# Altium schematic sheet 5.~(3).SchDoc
size 420 x 297 mm
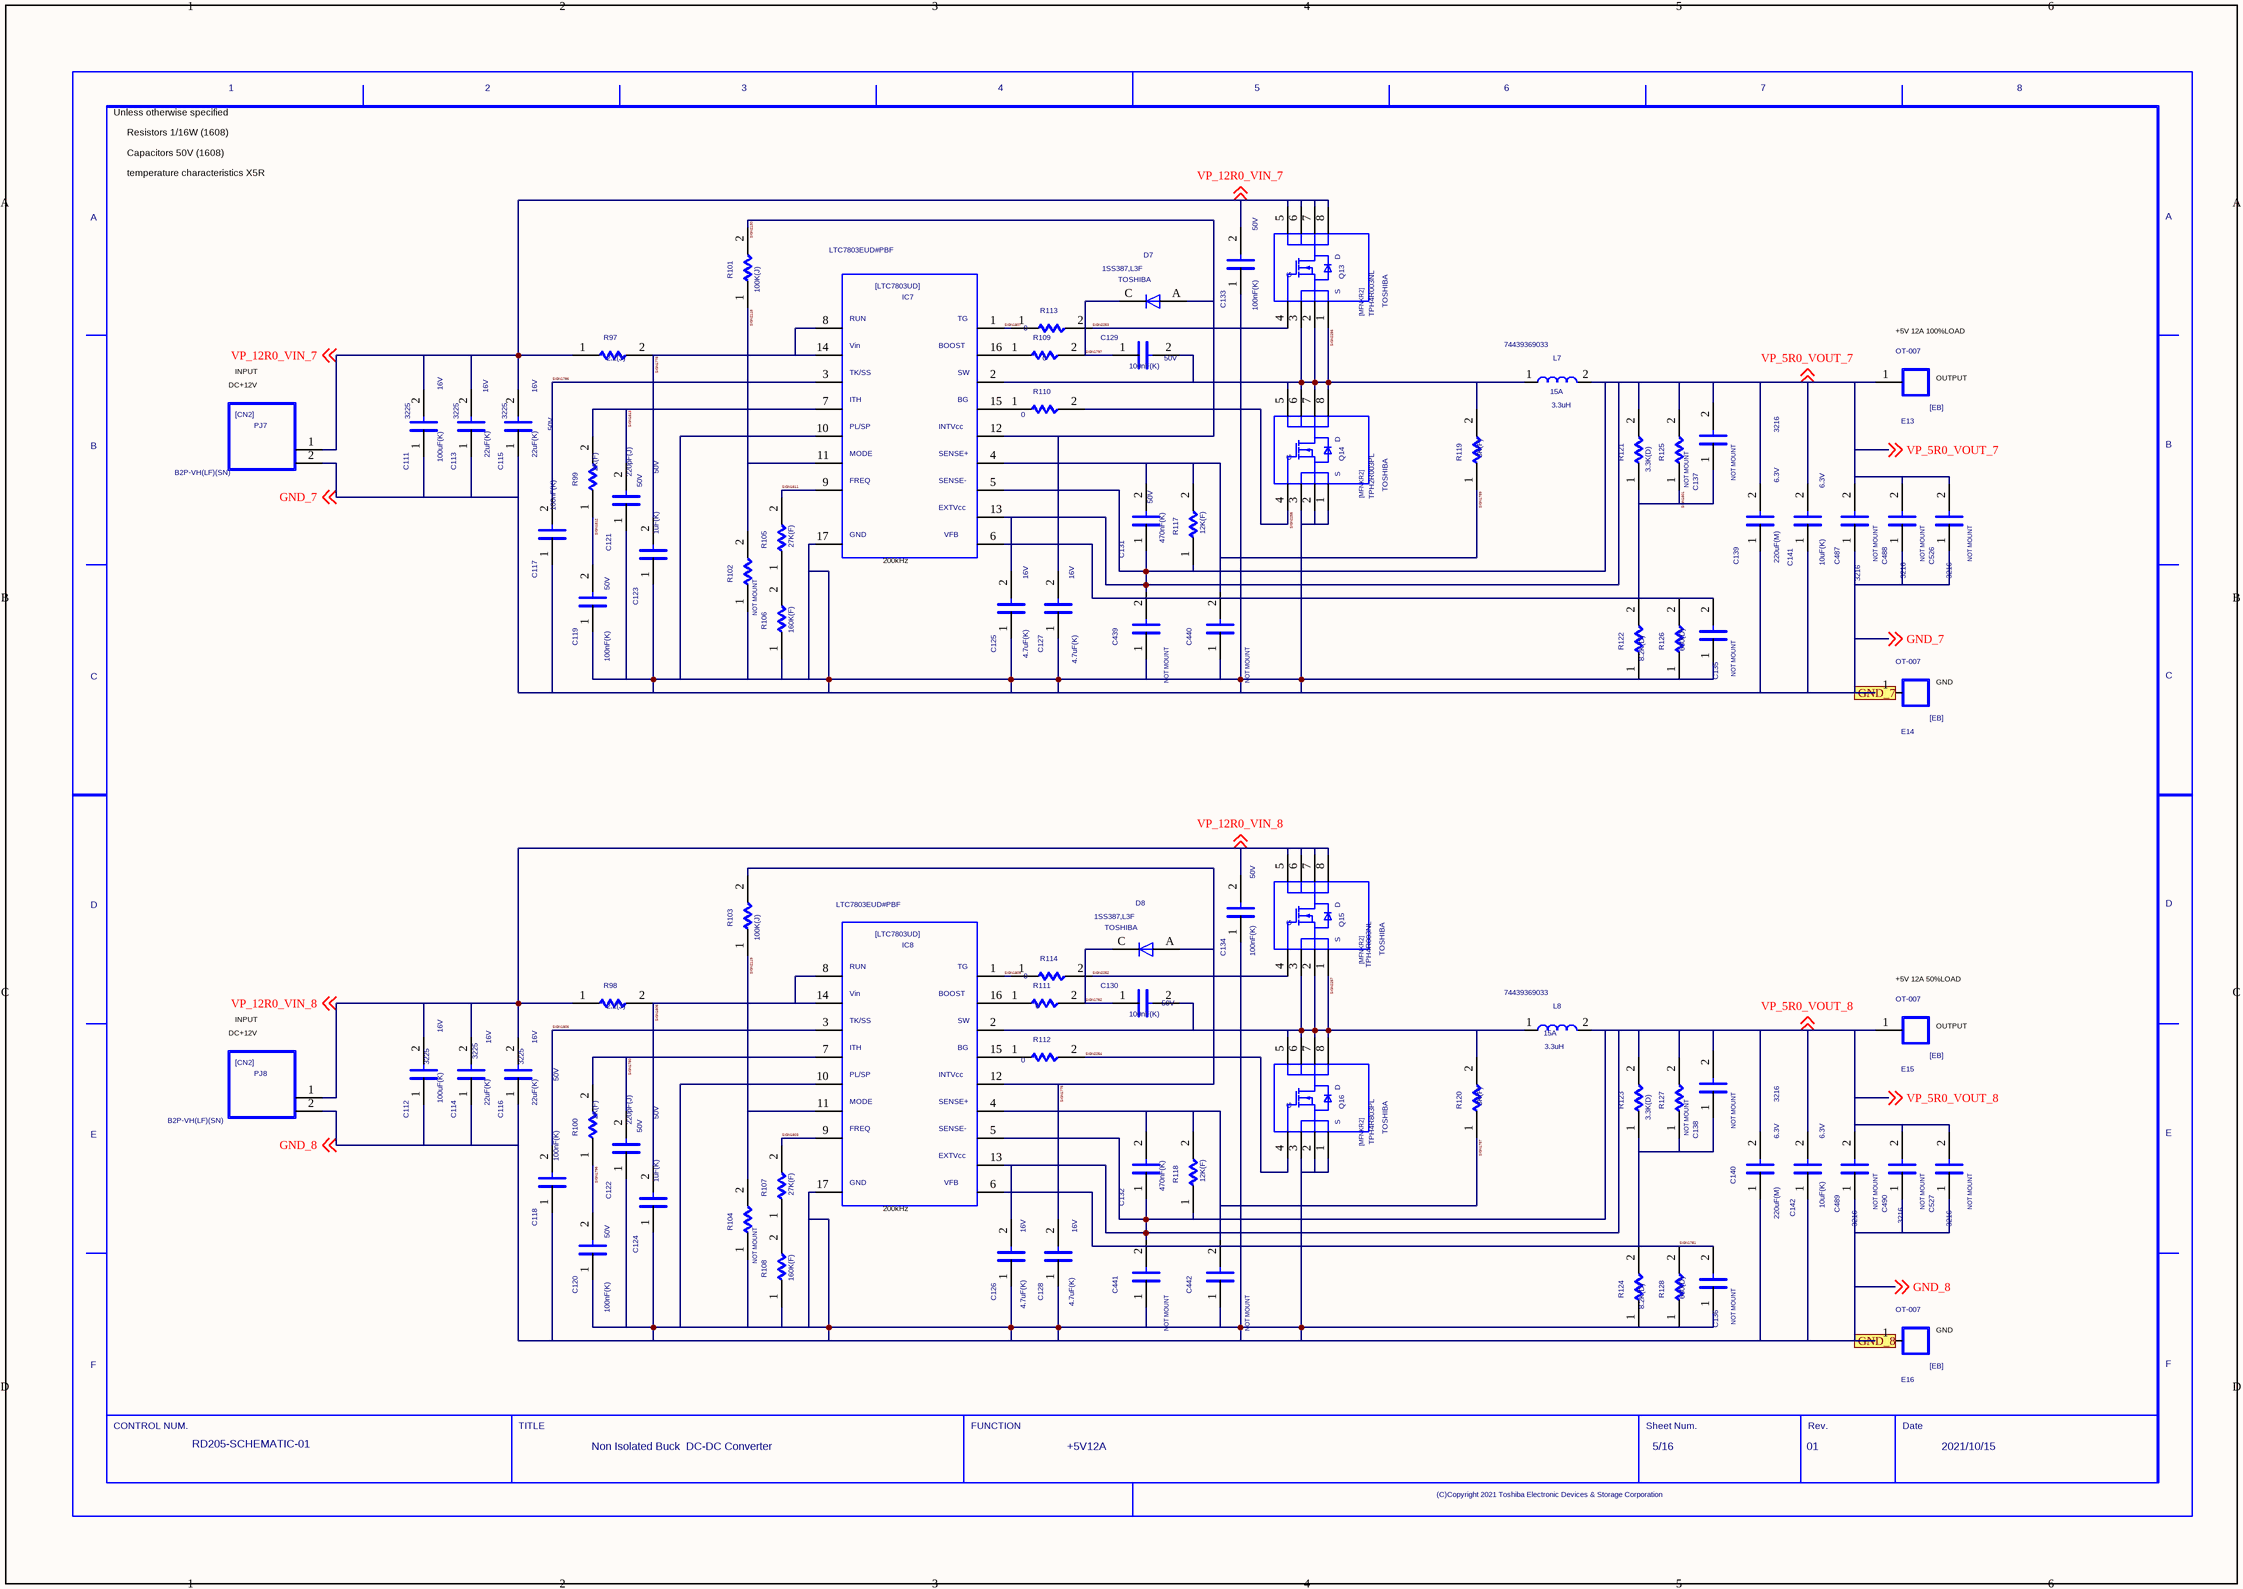
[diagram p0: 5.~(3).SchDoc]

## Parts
C111  SIZECODESMD: 3225  VAL2: 16V  VAL1: 100uF(K)  (hidden comment: C)
C112  SIZECODESMD: 3225  VAL2: 16V  VAL1: 100uF(K)  (hidden comment: C)
C113  SIZECODESMD: 3225  VAL2: 16V  VAL1: 22uF(K)  (hidden comment: C)
C114  SIZECODESMD: 3225  VAL2: 16V  VAL1: 22uF(K)  (hidden comment: C)
C115  SIZECODESMD: 3225  VAL2: 16V  VAL1: 22uF(K)  (hidden comment: C)
C116  SIZECODESMD: 3225  VAL2: 16V  VAL1: 22uF(K)  (hidden comment: C)
C117  VAL2: 50V  VAL1: 100nF(K)  (hidden comment: C)
C118  VAL2: 50V  VAL1: 100nF(K)  (hidden comment: C)
C119  VAL2: 50V  VAL1: 100nF(K)  (hidden comment: C)
C120  VAL2: 50V  VAL1: 100nF(K)  (hidden comment: C)
C121  VAL2: 50V  VAL1: 220pF(J)  (hidden comment: C)
C122  VAL2: 50V  VAL1: 220pF(J)  (hidden comment: C)
C123  VAL2: 50V  VAL1: 1uF(K)  (hidden comment: C)
C124  VAL2: 50V  VAL1: 1uF(K)  (hidden comment: C)
C125  VAL2: 16V  VAL1: 4.7uF(K)  (hidden comment: C)
C126  VAL2: 16V  VAL1: 4.7uF(K)  (hidden comment: C)
C127  VAL2: 16V  VAL1: 4.7uF(K)  (hidden comment: C)
C128  VAL2: 16V  VAL1: 4.7uF(K)  (hidden comment: C)
C129  VAL2: 50V  VAL1: 100nF(K)  (hidden comment: C)
C130  VAL2: 50V  VAL1: 100nF(K)  (hidden comment: C)
C131  VAL2: 50V  VAL1: 470nF(K)  (hidden comment: C)
C132  VAL1: 470nF(K)  (hidden comment: C)
C133  VAL2: 50V  VAL1: 100nF(K)  (hidden comment: C)
C134  VAL2: 50V  VAL1: 100nF(K)  (hidden comment: C)
C135  NOTMOUNT: NOT MOUNT  (hidden comment: C)
C136  NOTMOUNT: NOT MOUNT  (hidden comment: C)
C137  NOTMOUNT: NOT MOUNT  (hidden comment: C)
C138  NOTMOUNT: NOT MOUNT  (hidden comment: C)
C139  SIZECODESMD: 3216  VAL2: 6.3V  VAL1: 220uF(M)  (hidden comment: C)
C140  SIZECODESMD: 3216  VAL2: 6.3V  VAL1: 220uF(M)  (hidden comment: C)
C141  VAL2: 6.3V  VAL1: 10uF(K)  (hidden comment: C)
C142  VAL2: 6.3V  VAL1: 10uF(K)  (hidden comment: C)
C439  NOTMOUNT: NOT MOUNT  (hidden comment: C)
C440  NOTMOUNT: NOT MOUNT  (hidden comment: C)
C441  NOTMOUNT: NOT MOUNT  (hidden comment: C)
C442  NOTMOUNT: NOT MOUNT  (hidden comment: C)
C487  NOTMOUNT: NOT MOUNT  SIZECODESMD: 3216  (hidden comment: C)
C488  NOTMOUNT: NOT MOUNT  SIZECODESMD: 3216  (hidden comment: C)
C489  NOTMOUNT: NOT MOUNT  SIZECODESMD: 3216  (hidden comment: C)
C490  NOTMOUNT: NOT MOUNT  SIZECODESMD: 3216  (hidden comment: C)
C526  NOTMOUNT: NOT MOUNT  SIZECODESMD: 3216  (hidden comment: C)
C527  NOTMOUNT: NOT MOUNT  SIZECODESMD: 3216  (hidden comment: C)
D7  USERCOMPTEXT3: TOSHIBA  VAL3: 1SS387,L3F  (hidden comment: D)
D8  USERCOMPTEXT3: TOSHIBA  VAL3: 1SS387,L3F  (hidden comment: D)
E13  VAL3: OT-007  (hidden comment: EB)
E14  VAL3: OT-007  (hidden comment: EB)
E15  VAL3: OT-007  (hidden comment: EB)
E16  VAL3: OT-007  (hidden comment: EB)
IC7  VAL3: LTC7803EUD#PBF  (hidden comment: LTC7803UD)
IC8  VAL3: LTC7803EUD#PBF  (hidden comment: LTC7803UD)
L7  VAL3: 74439369033  VAL2: 15A  VAL1: 3.3uH  (hidden comment: L)
L8  VAL3: 74439369033  VAL2: 15A  VAL1: 3.3uH  (hidden comment: L)
PJ7  VAL3: B2P-VH(LF)(SN)  (hidden comment: CN2)
PJ8  VAL3: B2P-VH(LF)(SN)  (hidden comment: CN2)
Q13  USERCOMPTEXT3: TOSHIBA  VAL3: TPH4R003NL  (hidden comment: MFNKR2)
Q14  USERCOMPTEXT3: TOSHIBA  VAL3: TPH2R003PL  (hidden comment: MFNKR2)
Q15  USERCOMPTEXT3: TOSHIBA  VAL3: TPH4R003NL  (hidden comment: MFNKR2)
Q16  USERCOMPTEXT3: TOSHIBA  VAL3: TPH4R803PL  (hidden comment: MFNKR2)
R97  VAL1: 2.2(J)  (hidden comment: R)
R98  VAL1: 2.2(J)  (hidden comment: R)
R99  VAL1: 2K(F)  (hidden comment: R)
R100  VAL1: 2K(F)  (hidden comment: R)
R101  VAL1: 100K(J)  (hidden comment: R)
R102  NOTMOUNT: NOT MOUNT  (hidden comment: R)
R103  VAL1: 100K(J)  (hidden comment: R)
R104  NOTMOUNT: NOT MOUNT  (hidden comment: R)
R105  VAL1: 27K(F)  (hidden comment: R)
R106  VAL1: 160K(F)  (hidden comment: R)
R107  VAL1: 27K(F)  (hidden comment: R)
R108  VAL1: 160K(F)  (hidden comment: R)
R109  VAL1: 0  (hidden comment: R)
R110  VAL1: 0  (hidden comment: R)
R111  VAL1: 0  (hidden comment: R)
R112  VAL1: 0  (hidden comment: R)
R113  VAL1: 0  (hidden comment: R)
R114  VAL1: 0  (hidden comment: R)
R117  VAL1: 12K(F)  (hidden comment: R)
R118  VAL1: 12K(F)  (hidden comment: R)
R119  VAL1: 3K(F)  (hidden comment: R)
R120  VAL1: 3K(F)  (hidden comment: R)
R121  VAL1: 3.3K(D)  (hidden comment: R)
R122  VAL1: 8.2K(D)  (hidden comment: R)
R123  VAL1: 3.3K(D)  (hidden comment: R)
R124  VAL1: 8.2K(D)  (hidden comment: R)
R125  NOTMOUNT: NOT MOUNT  (hidden comment: R)
R126  VAL1: 680(D)  (hidden comment: R)
R127  NOTMOUNT: NOT MOUNT  (hidden comment: R)
R128  VAL1: 680(D)  (hidden comment: R)
U?  DATE: 2021/10/15  SHEETNUMBER: 5/16  TITLE: Non Isolated Buck / DC-DC Converter  REVISION: 01  DRAWINGNUMBER: RD205-SCHEMATIC-01  FUNCTION: +5V12A  (hidden comment: WAKU_DEF100)

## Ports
GND_7, GND_8

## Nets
GND_7: C111.1 C113.1 C115.1 C117.1 C119.1 C121.1 C123.1 C125.1 C127.1 C133.1 C135.1 C139.1 C141.1 C439.1 C440.1 C487.1 C488.1 C526.1 E14.1 IC7.10 IC7.17 PJ7.2 Q14.1 Q14.2 Q14.3 R102.1 R106.1 R122.1 R126.1 ; off-sheet GND_7, port GND_7
GND_8: C112.1 C114.1 C116.1 C118.1 C120.1 C122.1 C124.1 C126.1 C128.1 C134.1 C136.1 C140.1 C142.1 C441.1 C442.1 C489.1 C490.1 C527.1 E16.1 IC8.10 IC8.17 PJ8.2 Q16.1 Q16.2 Q16.3 R104.1 R108.1 R124.1 R128.1 ; off-sheet GND_8, port GND_8
SIGN1775: C128.2 D8.A IC8.12 R103.2
SIGN1778: C123.2 IC7.8 IC7.14 R97.2
SIGN1780: C122.2 IC8.7 R100.2
SIGN1781: C136.2 C138.1 IC8.6 R123.1 R124.2 R127.1 R128.2
SIGN1782: C130.1 D8.C R111.2
SIGN1786: C117.2 IC7.3
SIGN1787: C132.2 C442.2 IC8.4 R118.2 R120.1
SIGN1789: C131.2 C440.2 IC7.4 R117.2 R119.1
SIGN1796: C120.2 R100.1
SIGN1797: C129.1 D7.C R109.2
SIGN1801: C135.2 C137.1 IC7.6 R121.1 R122.2 R125.1 R126.2
SIGN1803: IC8.9 R107.2
SIGN1805: C124.2 IC8.8 IC8.14 R98.2
SIGN1806: C118.2 IC8.3
SIGN1807: IC7.1 R113.1
SIGN1809: IC8.1 R114.1
SIGN1811: IC7.9 R105.2
SIGN1812: C119.2 R99.1
SIGN1813: C121.2 IC7.7 R99.2
SIGN2118: IC7.11 R101.1 R102.2
SIGN2119: IC8.11 R103.1 R104.2
SIGN2130: C127.2 D7.A IC7.12 R101.2
SIGN2252: Q15.4 R114.2
SIGN2253: Q13.4 R113.2
SIGN2254: Q16.4 R112.2
SIGN2255: Q14.4 R110.2
SIGN2256: C129.2 IC7.2 L7.1 Q13.1 Q13.2 Q13.3 Q14.5 Q14.6 Q14.7 Q14.8 R119.2
SIGN2257: C130.2 IC8.2 L8.1 Q15.1 Q15.2 Q15.3 Q16.5 Q16.6 Q16.7 Q16.8 R120.2
VP_5R0_VOUT_7: C125.2 C131.1 C137.2 C139.2 C141.2 C439.2 C487.2 C488.2 C526.2 E13.1 IC7.5 IC7.13 L7.2 R117.1 R121.2 R125.2 ; off-sheet VP_5R0_VOUT_7
VP_5R0_VOUT_8: C126.2 C132.1 C138.2 C140.2 C142.2 C441.2 C489.2 C490.2 C527.2 E15.1 IC8.5 IC8.13 L8.2 R118.1 R123.2 R127.2 ; off-sheet VP_5R0_VOUT_8
VP_12R0_VIN_7: C111.2 C113.2 C115.2 C133.2 PJ7.1 Q13.5 Q13.6 Q13.7 Q13.8 R97.1 ; off-sheet VP_12R0_VIN_7
VP_12R0_VIN_8: C112.2 C114.2 C116.2 C134.2 PJ8.1 Q15.5 Q15.6 Q15.7 Q15.8 R98.1 ; off-sheet VP_12R0_VIN_8
NetIC7_15: IC7.15 R110.1
NetIC7_16: IC7.16 R109.1
NetIC8_15: IC8.15 R112.1
NetIC8_16: IC8.16 R111.1
NetR105_1: R105.1 R106.2
NetR107_1: R107.1 R108.2

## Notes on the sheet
- Unless otherwise specified
- Resistors 1/16W (1608)
- Capacitors 50V (1608)
- temperature characteristics X5R
- DC+12V
- INPUT
- (near E13) +5V 12A 100%LOAD
- (near E13) OUTPUT
- (near IC7) 200kHz
- (near E14) GND
- (near E15) +5V 12A 50%LOAD
- (near E15) OUTPUT
- (near IC8) 200kHz
- (near E16) GND

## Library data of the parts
C111 C112 = C: SQ_PART_MODEL: CON_100n; FNPARTSNAMEG: CHIP CERAMIC CAPACITOR (3225); USEINPARTSLIST: YES; OriginalSymbolOrigin: (2540,7620); MFSOLDERINGPROP: .; TEMPCHARACTERI2: B; MFFORMINGDIVP: KC; OUMECLASSIFICATION: セラミックコンデンサ; MFMOUNTSYMBOLP: 90; CDMASTERCADCELG: DC903A; PCODE: P03276001115; FNCLASSCODEG: P03-03; MAXGCOUNT: 1; RATEDVOLTAGE: 250; COMPONENTNAME: G36030160049; OUMEMAKER: KYC 京セラ; MFPACKAGEMETHOP: S; NOMINALCAPACITA: 100n; OUMEMAKERKATAMEI: CF32W5R104K250AT; CAPACITANCETOLE: K
C113-C116 = C: SQ_PART_MODEL: CON_22u; FNPARTSNAMEG: CHIP CERAMIC CAPACITOR (3225); USEINPARTSLIST: YES; OriginalSymbolOrigin: (2540,7620); MFSOLDERINGPROP: .; TEMPCHARACTERI2: B; MFFORMINGDIVP: KC; OUMECLASSIFICATION: セラミックコンデンサ; MFMOUNTSYMBOLP: 80; CDMASTERCADCELG: DC903A; PCODE: P03043035626; FNCLASSCODEG: P03-03; MAXGCOUNT: 1; RATEDVOLTAGE: 6.3; COMPONENTNAME: G36030119054; OUMEMAKER: TYD 太陽誘電; MFPACKAGEMETHOP: S; NOMINALCAPACITA: 22u; OUMEMAKERKATAMEI: JMK325BJ226KM-T; CAPACITANCETOLE: K
C117-C120 C129 C130 C133 C134 = C: SQ_PART_MODEL: CON_100n; FNPARTSNAMEG: CHIP CERAMIC CAPACITOR (1608); USEINPARTSLIST: YES; OriginalSymbolOrigin: (2540,7620); MFSOLDERINGPROP: .; TEMPCHARACTERI2: B; MFFORMINGDIVP: KC; OUMECLASSIFICATION: セラミックコンデンサ; SIZECODESMD: 1608; MFMOUNTSYMBOLP: 80; CDMASTERCADCELG: C8100E; PCODE: P03B000000E4; FNCLASSCODEG: P03-03; MAXGCOUNT: 1; RATEDVOLTAGE: 16; COMPONENTNAME: GDM030000598; OUMEMAKER: MRT 村田製作所; MFPACKAGEMETHOP: S; NOMINALCAPACITA: 100n; OUMEMAKERKATAMEI: GRM188B11C104KA01C; CAPACITANCETOLE: K
C121 = C: SQ_PART_MODEL: CON_220p; FNPARTSNAMEG: CHIP CERAMIC CAPACITOR (1608); USEINPARTSLIST: YES; OriginalSymbolOrigin: (2540,7620); CDMASTERCADCELG: C8100E; MFSOLDERINGPROP: .; TEMPCHARACTERI2: CH; MFFORMINGDIVP: KC; OUMECLASSIFICATION: セラミックコンデンサ; SIZECODESMD: 1608; MFMOUNTSYMBOLP: 80; PCODE: P03039269127; FNCLASSCODEG: P03-03; MAXGCOUNT: 1; RATEDVOLTAGE: 50; COMPONENTNAME: G36030011488; OUMEMAKER: KYC 京セラ; MFPACKAGEMETHOP: S; NOMINALCAPACITA: 220p; OUMEMAKERKATAMEI: CM105CH221J50AT; CAPACITANCETOLE: J
C122 = C: SQ_PART_MODEL: CON_220p; FNPARTSNAMEG: CHIP CERAMIC CAPACITOR (1608); USEINPARTSLIST: YES; OriginalSymbolOrigin: (2540,7620); MFSOLDERINGPROP: .; TEMPCHARACTERI2: CH; MFFORMINGDIVP: KC; OUMECLASSIFICATION: セラミックコンデンサ; SIZECODESMD: 1608; MFMOUNTSYMBOLP: 80; CDMASTERCADCELG: C8100E; PCODE: P03039269127; FNCLASSCODEG: P03-03; MAXGCOUNT: 1; RATEDVOLTAGE: 50; COMPONENTNAME: G36030011488; OUMEMAKER: KYC 京セラ; MFPACKAGEMETHOP: S; NOMINALCAPACITA: 220p; OUMEMAKERKATAMEI: CM105CH221J50AT; CAPACITANCETOLE: J
C123 C124 = C: SQ_PART_MODEL: CON_1u; FNPARTSNAMEG: CHIP CERAMIC CAPACITOR (1608); USEINPARTSLIST: YES; OriginalSymbolOrigin: (2540,7620); MFSOLDERINGPROP: .; TEMPCHARACTERI2: B; MFFORMINGDIVP: KC; OUMECLASSIFICATION: セラミックコンデンサ; SIZECODESMD: 1608; MFMOUNTSYMBOLP: 80; CDMASTERCADCELG: C8100E; PCODE: P03039ACE122; FNCLASSCODEG: P03-03; MAXGCOUNT: 1; RATEDVOLTAGE: 6.3; COMPONENTNAME: G36030104159; OUMEMAKER: KYC 京セラ; MFPACKAGEMETHOP: S; NOMINALCAPACITA: 1u; OUMEMAKERKATAMEI: CM105B105K06ATN; CAPACITANCETOLE: K
C125 C126 = C: SQ_PART_MODEL: CON_4.7u; FNPARTSNAMEG: CHIP CERAMIC CAPACITOR (1608); USEINPARTSLIST: YES; OriginalSymbolOrigin: (2540,7620); PCODE: P03B000000MS; MFSOLDERINGPROP: .; TEMPCHARACTERI2: B; MFFORMINGDIVP: KC; OUMECLASSIFICATION: セラミックコンデンサ; SIZECODESMD: 1608; MFMOUNTSYMBOLP: 80; CDMASTERCADCELG: C8100E; FNCLASSCODEG: P03-03; MAXGCOUNT: 1; RATEDVOLTAGE: 4; COMPONENTNAME: GDM030000053; OUMEMAKER: KYC 京セラ; MFPACKAGEMETHOP: S; NOMINALCAPACITA: 4.7u; OUMEMAKERKATAMEI: CM105B475M04AT; CAPACITANCETOLE: M
C127 C128 = C: SQ_PART_MODEL: CON_4.7u; FNPARTSNAMEG: CHIP CERAMIC CAPACITOR (1608); USEINPARTSLIST: YES; OriginalSymbolOrigin: (2540,7620); MFSOLDERINGPROP: .; TEMPCHARACTERI2: B; MFFORMINGDIVP: KC; OUMECLASSIFICATION: セラミックコンデンサ; SIZECODESMD: 1608; MFMOUNTSYMBOLP: 80; CDMASTERCADCELG: C8100E; PCODE: P03B000000MS; FNCLASSCODEG: P03-03; MAXGCOUNT: 1; RATEDVOLTAGE: 4; COMPONENTNAME: GDM030000053; OUMEMAKER: KYC 京セラ; MFPACKAGEMETHOP: S; NOMINALCAPACITA: 4.7u; OUMEMAKERKATAMEI: CM105B475M04AT; CAPACITANCETOLE: M
C131 = C: SQ_PART_MODEL: CON_470n; FNPARTSNAMEG: CHIP CERAMIC CAPACITOR (1608); USEINPARTSLIST: YES; OriginalSymbolOrigin: (2540,7620); MFSOLDERINGPROP: .; TEMPCHARACTERI2: B; MFFORMINGDIVP: KC; OUMECLASSIFICATION: セラミックコンデンサ; SIZECODESMD: 1608; MFMOUNTSYMBOLP: 80; CDMASTERCADCELG: C8100E; PCODE: P03039ABG127; FNCLASSCODEG: P03-03; MAXGCOUNT: 1; RATEDVOLTAGE: 10; COMPONENTNAME: GDM030001129; OUMEMAKER: KYC 京セラ; MFPACKAGEMETHOP: S; NOMINALCAPACITA: 470n; OUMEMAKERKATAMEI: CM105B474K10AT; CAPACITANCETOLE: K
C132 = C: SQ_PART_MODEL: CON_470n; FNPARTSNAMEG: CHIP CERAMIC CAPACITOR (1608); USEINPARTSLIST: YES; OriginalSymbolOrigin: (2540,7620); MFSOLDERINGPROP: .; TEMPCHARACTERI2: B; MFFORMINGDIVP: KC; OUMECLASSIFICATION: セラミックコンデンサ; SIZECODESMD: 1608; MFMOUNTSYMBOLP: 80; CDMASTERCADCELG: C8100E; PCODE: P03039ABG127; FNCLASSCODEG: P03-03; MAXGCOUNT: 1; RATEDVOLTAGE: 10; COMPONENTNAME: GDM030001129; OUMEMAKER: KYC 京セラ; MFPACKAGEMETHOP: S; NOMINALCAPACITA: 470n; OUMEMAKERKATAMEI: CM105B474K10AT; VAL2: 50V; CAPACITANCETOLE: K
C135-C138 = C: SQ_PART_MODEL: CON_100p; FNPARTSNAMEG: CHIP CERAMIC CAPACITOR (1608); USEINPARTSLIST: YES; OriginalSymbolOrigin: (2540,7620); TOLERANCE: J; ASIMVALUE: 100P; MFSOLDERINGPROP: .; TEMPCHARACTERI2: CH; MFFORMINGDIVP: KC; OUMECLASSIFICATION: セラミックコンデンサ; SIZECODESMD: 1608; MFMOUNTSYMBOLP: 80; CDMASTERCADCELG: C8100E; PCODE: P03039177125; FNCLASSCODEG: P03-03; MAXGCOUNT: 1; RATEDVOLTAGE: 50; COMPONENTNAME: G36030011365; OUMEMAKER: KYC 京セラ; MFPACKAGEMETHOP: S; OUMEMAKERKATAMEI: CM105CH101J50AT; VAL2: 50V; VAL1: 100pF(J)
C139 C140 = C: SQ_PART_MODEL: CON_22u; FNPARTSNAMEG: CHIP CERAMIC CAPACITOR (3216); USEINPARTSLIST: YES; OriginalSymbolOrigin: (2540,7620); MFSOLDERINGPROP: .; TEMPCHARACTERI2: B; MFFORMINGDIVP: KC; OUMECLASSIFICATION: セラミックコンデンサ; MFMOUNTSYMBOLP: 80; CDMASTERCADCELG: DC901A; PCODE: P03B0000004V; FNCLASSCODEG: P03-03; MAXGCOUNT: 1; RATEDVOLTAGE: 6.3; COMPONENTNAME: GDM030000020; OUMEMAKER: KYC 京セラ; MFPACKAGEMETHOP: S; NOMINALCAPACITA: 22u; OUMEMAKERKATAMEI: CM316B226M06AT; CAPACITANCETOLE: M
C141 C142 = C: SQ_PART_MODEL: CON_1u; FNPARTSNAMEG: CHIP CERAMIC CAPACITOR (1608); PARTCOMMENT: 代表セル<KC0008> がフットプリントに登録されていません。; USEINPARTSLIST: YES; OriginalSymbolOrigin: (2540,7620); MFSOLDERINGPROP: .; TEMPCHARACTERI2: B; MFFORMINGDIVP: KC; OUMECLASSIFICATION: セラミックコンデンサ; SIZECODESMD: 1608; MFMOUNTSYMBOLP: 80; CDMASTERCADCELG: KC0008; PCODE: P03B000000ZQ; FNCLASSCODEG: P03-03; MAXGCOUNT: 1; RATEDVOLTAGE: 6.3; COMPONENTNAME: GDM030000202; OUMEMAKER: MRT 村田製作所; MFPACKAGEMETHOP: S; NOMINALCAPACITA: 1u; OUMEMAKERKATAMEI: GRM185B10J105KE21D; CAPACITANCETOLE: K
C439-C442 = C: SQ_PART_MODEL: CON_220n; FNPARTSNAMEG: CHIP CERAMIC CAPACITOR (1608); PARTCOMMENT: 代表セル<KC0008> がフットプリントに登録されていません。; USEINPARTSLIST: YES; OriginalSymbolOrigin: (2540,7620); MFSOLDERINGPROP: .; TEMPCHARACTERI2: B; MFFORMINGDIVP: KC; OUMECLASSIFICATION: セラミックコンデンサ; SIZECODESMD: 1608; MFMOUNTSYMBOLP: 80; CDMASTERCADCELG: KC0008; PCODE: P03B000001L3; FNCLASSCODEG: P03-03; MAXGCOUNT: 1; RATEDVOLTAGE: 16; COMPONENTNAME: GDM030001129; OUMEMAKER: MRT 村田製作所; MFPACKAGEMETHOP: S; NOMINALCAPACITA: 220n; OUMEMAKERKATAMEI: GRM188B11C224KA01D; VAL2: 16V; VAL1: 220nF(K); CAPACITANCETOLE: K
C487-C490 C526 C527 = C: SQ_PART_MODEL: CON_22u; FNPARTSNAMEG: CHIP CERAMIC CAPACITOR (3216); USEINPARTSLIST: YES; OriginalSymbolOrigin: (2540,7620); MFSOLDERINGPROP: .; TEMPCHARACTERI2: B; MFFORMINGDIVP: KC; OUMECLASSIFICATION: セラミックコンデンサ; MFMOUNTSYMBOLP: 80; CDMASTERCADCELG: DC901A; PCODE: P03B0000004V; FNCLASSCODEG: P03-03; MAXGCOUNT: 1; RATEDVOLTAGE: 6.3; COMPONENTNAME: GDM030000020; OUMEMAKER: KYC 京セラ; MFPACKAGEMETHOP: S; NOMINALCAPACITA: 22u; OUMEMAKERKATAMEI: CM316B226M06AT; VAL2: 6.3V; VAL1: 22uF(M); CAPACITANCETOLE: M
D7 D8 = D: FNPARTSNAMEG: DIODE; USEINPARTSLIST: YES; PARTNAME: GDM420000143; SAVEAREA0: -565,-171,12979,8058; SAVECOUNT: 1; TIME: 14:49:55; UPDATEUSER: 19870035; UPDATETIME: 14:20:16; OriginalSymbolOrigin: (5080,5080); FORWARDVOLTAGEM: 0; MAXREVERSEVOLTA: 80; COMPONENTNAME: GDM420000143_package; MFSOLDERINGPROP: .; OUMEMAKER: TSB 東芝（ＹＰＳＳ）; QUADMODEL: dummymodel; MFPACKAGEMETHOP: S; MFFORMINGDIVP: MM; MOUNTINGFORMSMD: SMD; OUMECLASSIFICATION: 小信号ダイオード; OUMEMAKERKATAMEI: 1SS387(TPH3,F); CDMASTERCADCELG: D8101D; PCODE: P42B0000008E; FNCLASSCODEG: P42-01
E13-E16 = EB: FNPARTSNAMEG: TERMINAL; USEINPARTSLIST: YES; PARTNAME: 5P9L1232P001; OUMEPARTTYPE: TB; OriginalSymbolOrigin: (2540,12700); COMPONENTNAME: 5P9L1232P001_package; MAXGCOUNT: 1; MFSOLDERINGPROP: .; OUMEMAKER: オサダ; QUADMODEL: dummymodel; MFPACKAGEMETHOP: I; MFFORMINGDIVP: OD; OUMECLASSIFICATION: 端子台、端子板; CDMASTERCADCELG: DE0009; KIND: PBS; PCODE: P29045001117; TERMINALSTYLE: SC; FNCLASSCODEG: P29-01
IC7 IC8 = LTC7803UD: USEINPARTSLIST: YES; SAVECOUNT: 29; SAVEAREA0: -53177,0,89020,58420; TIME: 16:14:14; UPDATEUSER: q91866sr; UPDATETIME: 13:15:36; OriginalSymbolOrigin: (5080,55880); MAXGCOUNT: 1; COMPONENTNAME: LTC7803UD_LTC7803UD; OUMEMAKER: ANALOG DEVICES
L7 L8 = L: USEINPARTSLIST: YES; OriginalSymbolOrigin: (2540,5080); MAXGCOUNT: 1; COMPONENTNAME: L_L; OUMEMAKER: WURTH
PJ7 PJ8 = CN2: FNPARTSNAMEG: 3.96PITCH NYLON CONNECTOR; USEINPARTSLIST: YES; PARTNAME: G36220114012; OUMEPARTTYPE: CN; OriginalSymbolOrigin: (2540,15240); MAXGCOUNT: 1; RATEDCURRENT: 7; COMPONENTNAME: G36220114012_package; MFSOLDERINGPROP: .; OUMEMAKER: JST 日本圧着端子製造; NUMBEROFCONTACT: 2; QUADMODEL: dummymodel; MFPACKAGEMETHOP: I; MFFORMINGDIVP: CU; CONTACTPITCH: 3.96m; OUMEMAKERKATAMEI: B2P-VH; CDMASTERCADCELG: DPJ514; PCODE: P22346001114; TERMINALSTYLE: PW; FNCLASSCODEG: P22-10
Q13-Q16 = MFNKR2: USEINPARTSLIST: YES; PARTNAME: TPH6R003NL; SAVEAREA0: -9199,-39,32138,22820; TIME: 18:57:44; UPDATEUSER: q91866sr; UPDATETIME: 12:36:02; SAVECOUNT: 10; OriginalSymbolOrigin: (5080,20320); MAXGCOUNT: 1; COMPONENTNAME: MFNKR2_MFNKR2
R97 R98 = R: SQ_PART_MODEL: RES_2.2; FNPARTSNAMEG: CHIP RESISTOR (1608); USEINPARTSLIST: YES; OriginalSymbolOrigin: (5080,5080); TOLERANCE: J; ASIMVALUE: 2.2; MAXGCOUNT: 1; COMPONENTNAME: G36010011507; MFSOLDERINGPROP: .; OUMEMAKER: NAE 松下電子部品; MFPACKAGEMETHOP: S; MFFORMINGDIVP: KC; MOUNTINGFORMSMD: SMD; OUMECLASSIFICATION: 表面実装用固定抵抗器; MFMOUNTSYMBOLP: 80; POWERRATING: 63m; OUMEMAKERKATAMEI: ERJ3GEYJ2R2V; NUMBEROFELEMENT: 0; VAL2: 62.5mW; CDMASTERCADCELG: DR802R; PCODE: P01042157622; FNCLASSCODEG: P01-08
R99 R100 = R: SQ_PART_MODEL: RES_2K; FNPARTSNAMEG: CHIP RESISTOR (1608); USEINPARTSLIST: YES; OriginalSymbolOrigin: (5080,5080); MAXGCOUNT: 1; COMPONENTNAME: G36010027A10; MFSOLDERINGPROP: .; OUMEMAKER: KAM 釜屋電機; MFPACKAGEMETHOP: S; MFFORMINGDIVP: KC; MOUNTINGFORMSMD: SMD; OUMECLASSIFICATION: 表面実装用固定抵抗器; RESISTANCETOLER: F; MFMOUNTSYMBOLP: 80; POWERRATING: 63m; OUMEMAKERKATAMEI: RMC1/16-202FTP; NOMINALRESISTAN: 2K; NUMBEROFELEMENT: 0; VAL2: 62.5mW; CDMASTERCADCELG: DR802R; PCODE: P01042243325; FNCLASSCODEG: P01-08
R101 R103 = R: SQ_PART_MODEL: RES_100K; FNPARTSNAMEG: CHIP RESISTOR (1608); USEINPARTSLIST: YES; OriginalSymbolOrigin: (5080,5080); TOLERANCE: J; ASIMVALUE: 100K; MFSOLDERINGPROP: .; MFPACKAGEMETHOP: S; MFFORMINGDIVP: KC; MOUNTINGFORMSMD: SMD; MFMOUNTSYMBOLP: 80; NUMBEROFELEMENT: 0; PCODE: P01042047220; MAXGCOUNT: 1; COMPONENTNAME: G36010011057; OUMEMAKER: HDK 北陸電気工業; OUMECLASSIFICATION: 表面実装用固定抵抗器; POWERRATING: 63m; OUMEMAKERKATAMEI: CR1/16 104JV; VAL2: 62.5mW; CDMASTERCADCELG: DR802R; FNCLASSCODEG: P01-08
R102 R104 = R: SQ_PART_MODEL: RES_10; FNPARTSNAMEG: CHIP RESISTOR (1608); USEINPARTSLIST: YES; OriginalSymbolOrigin: (5080,5080); TOLERANCE: F; ASIMVALUE: 10; MFSOLDERINGPROP: .; MFPACKAGEMETHOP: S; MFFORMINGDIVP: KC; MOUNTINGFORMSMD: SMD; MFMOUNTSYMBOLP: 80; NUMBEROFELEMENT: 0; PCODE: P01042036620; MAXGCOUNT: 1; COMPONENTNAME: G36010104063; OUMEMAKER: NAE 松下電子部品; OUMECLASSIFICATION: 表面実装用固定抵抗器; POWERRATING: 63m; OUMEMAKERKATAMEI: ERJ3GEYF100V; VAL2: 62.5mW; VAL1: 10(F); CDMASTERCADCELG: DR802R; FNCLASSCODEG: P01-08
R105 R107 = R: SQ_PART_MODEL: RES_27K; FNPARTSNAMEG: CHIP RESISTOR (1608); USEINPARTSLIST: YES; OriginalSymbolOrigin: (5080,5080); MAXGCOUNT: 1; TOLERANCE: F; COMPONENTNAME: G36010027195; MFSOLDERINGPROP: .; OUMEMAKER: NAE 松下電子部品; MFPACKAGEMETHOP: S; MFFORMINGDIVP: KC; MOUNTINGFORMSMD: SMD; OUMECLASSIFICATION: 表面実装用固定抵抗器; ASIMVALUE: 27K; MFMOUNTSYMBOLP: 80; POWERRATING: 63m; OUMEMAKERKATAMEI: ERJ3GEYF273V; NUMBEROFELEMENT: 0; VAL2: 62.5mW; CDMASTERCADCELG: DR802R; PCODE: P01042508622; FNCLASSCODEG: P01-08
R106 R108 = R: SQ_PART_MODEL: RES_160K; FNPARTSNAMEG: CHIP RESISTOR (1608); USEINPARTSLIST: YES; OriginalSymbolOrigin: (5080,5080); MAXGCOUNT: 1; COMPONENTNAME: G51011061108; MFSOLDERINGPROP: .; OUMEMAKER: HDK 北陸電気工業; MFPACKAGEMETHOP: S; MFFORMINGDIVP: KC; MOUNTINGFORMSMD: SMD; OUMECLASSIFICATION: 表面実装用固定抵抗器; RESISTANCETOLER: F; MFMOUNTSYMBOLP: 80; POWERRATING: 63m; OUMEMAKERKATAMEI: CR1/16 164FV; NOMINALRESISTAN: 160K; NUMBEROFELEMENT: 0; VAL2: 62.5mW; CDMASTERCADCELG: DR802R; PCODE: P01042125225; FNCLASSCODEG: P01-08
R109 R111 = R: SQ_PART_MODEL: RES_10; FNPARTSNAMEG: CHIP RESISTOR (1608); USEINPARTSLIST: YES; OriginalSymbolOrigin: (5080,5080); TOLERANCE: F; ASIMVALUE: 10; MFSOLDERINGPROP: .; MFPACKAGEMETHOP: S; MFFORMINGDIVP: KC; MOUNTINGFORMSMD: SMD; MFMOUNTSYMBOLP: 80; PCODE: P01042036620; MAXGCOUNT: 1; COMPONENTNAME: G36010104063; OUMEMAKER: NAE 松下電子部品; OUMECLASSIFICATION: 表面実装用固定抵抗器; POWERRATING: 63m; OUMEMAKERKATAMEI: ERJ3GEYF100V; VAL2: 62.5mW; CDMASTERCADCELG: DR802R; FNCLASSCODEG: P01-08
R110 R112-R114 = R: SQ_PART_MODEL: RES_10; FNPARTSNAMEG: CHIP RESISTOR (2012); USEINPARTSLIST: YES; OriginalSymbolOrigin: (5080,5080); MAXGCOUNT: 1; TOLERANCE: F; COMPONENTNAME: 5P9L1083P100; MFSOLDERINGPROP: .; OUMEMAKER: 北陸電気工業; MFPACKAGEMETHOP: S; MFFORMINGDIVP: KC; MOUNTINGFORMSMD: SMD; OUMECLASSIFICATION: 表面実装用固定抵抗器; ASIMVALUE: 10; MFMOUNTSYMBOLP: 90; POWERRATING: 100m; OUMEMAKERKATAMEI: CR1/10 100FV Pb(F); VAL2: 125mW; CDMASTERCADCELG: DR910A; PCODE: P01043091222; FNCLASSCODEG: P01-08
R117 R118 = R: SQ_PART_MODEL: RES_12K; FNPARTSNAMEG: CHIP RESISTOR (1608); USEINPARTSLIST: YES; OriginalSymbolOrigin: (5080,5080); TOLERANCE: F; ASIMVALUE: 12K; MAXGCOUNT: 1; COMPONENTNAME: G36010027195; MFSOLDERINGPROP: .; OUMEMAKER: HDK 北陸電気工業; MFPACKAGEMETHOP: S; MFFORMINGDIVP: KC; MOUNTINGFORMSMD: SMD; OUMECLASSIFICATION: 表面実装用固定抵抗器; MFMOUNTSYMBOLP: 80; POWERRATING: 63m; OUMEMAKERKATAMEI: CR1/16 123FV; NUMBEROFELEMENT: 0; VAL2: 62.5mW; CDMASTERCADCELG: DR802R; PCODE: P01042514227; FNCLASSCODEG: P01-08
R119 R120 = R: SQ_PART_MODEL: RES_3K; FNPARTSNAMEG: CHIP RESISTOR (1608); USEINPARTSLIST: YES; OriginalSymbolOrigin: (5080,5080); MAXGCOUNT: 1; COMPONENTNAME: G36010027409; MFSOLDERINGPROP: .; OUMEMAKER: KOA ＫＯＡ; MFPACKAGEMETHOP: S; MFFORMINGDIVP: KC; MOUNTINGFORMSMD: SMD; OUMECLASSIFICATION: 表面実装用固定抵抗器; RESISTANCETOLER: F; MFMOUNTSYMBOLP: 80; POWERRATING: 63m; OUMEMAKERKATAMEI: RK73H1JTD3001F; NOMINALRESISTAN: 3K; NUMBEROFELEMENT: 0; VAL2: 62.5mW; CDMASTERCADCELG: DR802R; PCODE: P01042331428; FNCLASSCODEG: P01-08
R121 R123 = R: SQ_PART_MODEL: RES_3.3K; FNPARTSNAMEG: CHIP RESISTOR (1608); USEINPARTSLIST: YES; OriginalSymbolOrigin: (5080,5080); MAXGCOUNT: 1; COMPONENTNAME: G36010014485; MFSOLDERINGPROP: .; OUMEMAKER: SSM 進工業; MFPACKAGEMETHOP: S; MFFORMINGDIVP: KC; MOUNTINGFORMSMD: SMD; OUMECLASSIFICATION: 表面実装用固定抵抗器; RESISTANCETOLER: D; MFMOUNTSYMBOLP: 80; POWERRATING: 63m; OUMEMAKERKATAMEI: RR0816P-332-D; NOMINALRESISTAN: 3.3K; NUMBEROFELEMENT: 0; VAL2: 62.5mW; CDMASTERCADCELG: DR802R; PCODE: P01042249822; FNCLASSCODEG: P01-08
R122 R124 = R: ICX_PART_MODEL: RES_8.2K; FNPARTSNAMEG: CHIP RESISTOR (1608); OriginalSymbolOrigin: (5080,5080); FNCLASSCODEG: P01-08; PCODE: P01117051114; CDMASTERCADCELG: DR802R; USEWITHSCHEMA: YES; VAL2: 62.5mW; NUMBEROFELEMENT: 0; NOMINALRESISTAN: 8.2K; OUMEMAKERKATAMEI: RK73G1JTD822D; POWERRATING: 63m; MFMOUNTSYMBOLP: 80; RESISTANCETOLER: D; FUNCTION: G36010129479; OUMECLASSIFICATION: 表面実装用固定抵抗器; MOUNTINGFORMSMD: SMD; MFFORMINGDIVP: KC; MFPACKAGEMETHOP: S; OUMEMAKER: KOA ＫＯＡ; MFSOLDERINGPROP: .; MAXGCOUNT: 1
R125 R127 = R: SQ_PART_MODEL: RES_3.3K; FNPARTSNAMEG: CHIP RESISTOR (1608); USEINPARTSLIST: YES; OriginalSymbolOrigin: (5080,5080); TOLERANCE: F; ASIMVALUE: 3.3K; MAXGCOUNT: 1; COMPONENTNAME: G36010027027; MFSOLDERINGPROP: .; OUMEMAKER: ROH ロー・; MFPACKAGEMETHOP: S; MFFORMINGDIVP: KC; MOUNTINGFORMSMD: SMD; OUMECLASSIFICATION: 表面実装用固定抵抗器; MFMOUNTSYMBOLP: 80; POWERRATING: 63m; OUMEMAKERKATAMEI: MCR03EZPFX3301; NUMBEROFELEMENT: 0; VAL2: 62.5mW; VAL1: 3.3K(F); CDMASTERCADCELG: DR802R; PCODE: P01042250729; FNCLASSCODEG: P01-08
R126 R128 = R: ICX_PART_MODEL: RES_680; FNPARTSNAMEG: CHIP RESISTOR (1608); OriginalSymbolOrigin: (5080,5080); FNCLASSCODEG: P01-08; PCODE: P01117025115; CDMASTERCADCELG: DR802R; USEWITHSCHEMA: YES; VAL2: 62.5mW; NUMBEROFELEMENT: 0; NOMINALRESISTAN: 680; OUMEMAKERKATAMEI: RK73G1JTD681D; POWERRATING: 63m; MFMOUNTSYMBOLP: 80; RESISTANCETOLER: D; FUNCTION: G36010129219; OUMECLASSIFICATION: 表面実装用固定抵抗器; MOUNTINGFORMSMD: SMD; MFFORMINGDIVP: KC; MFPACKAGEMETHOP: S; OUMEMAKER: KOA ＫＯＡ; MFSOLDERINGPROP: .; MAXGCOUNT: 1
U? = WAKU_DEF100: PLOTTIME: HH:MM; SAVEAREA0: 330961,54,387907,31546; TIME: 19:23:07; UPDATEUSER: t5459927; UPDATETIME: 15:33:39; SAVECOUNT: 6; OriginalSymbolOrigin: (10160,284480); DESIGNED: ***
